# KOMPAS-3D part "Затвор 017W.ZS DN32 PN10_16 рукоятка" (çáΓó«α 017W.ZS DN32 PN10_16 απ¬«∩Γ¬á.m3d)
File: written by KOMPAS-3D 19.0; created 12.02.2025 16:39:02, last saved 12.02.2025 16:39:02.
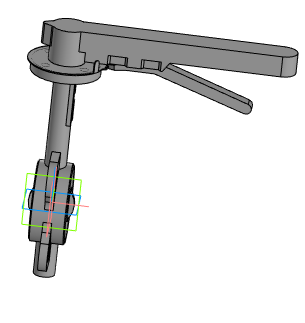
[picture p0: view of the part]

Document properties: Автор: Евгений; Полное имя файла: Затвор 017W.ZS DN32 PN10_16 рукоятка.a3d

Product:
- Part/product: Затвор 017W.ZS DN32 PN10_16 рукоятка
    Масса: 3.0546

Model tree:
1. Операция без истории:1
